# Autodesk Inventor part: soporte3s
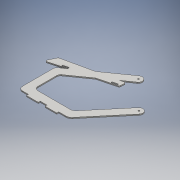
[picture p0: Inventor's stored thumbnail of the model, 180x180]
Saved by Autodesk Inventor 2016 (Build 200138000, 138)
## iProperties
Created: 2016-06
Part Number: soporte3s
Material: Genérico
Document SubType Name: Modeling
Designer: adm
Density: 1 g/cm^3
Appearance: Valor por defecto
Author: adm
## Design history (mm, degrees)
sketch "Boceto1"
  geometry: L1 (-161.273, -190.979)-(3.65, -190.979); L2 (-109.73, -230.979)-(-75.003, -230.979); L3 (-109.73, -230.979)-(-75.003, -230.979); L4 (-75.003, -230.979)-(-75.003, -240.979); L5 (-75.003, -230.979)-(-75.003, -240.979); L6 (-75.003, -240.979)-(-15.003, -240.979); L7 (-75.003, -240.979)-(-15.003, -240.979); L8 (-15.003, -240.979)-(-15.003, -230.979); L9 (-15.003, -240.979)-(-15.003, -230.979); L10 (-15.003, -230.979)-(22.302, -230.979); L11 (-109.73, -240.979)-(-109.73, -230.979); L12 (-181.273, -74.736)-(-181.273, -170.979); L13 (-221.273, -54.025)-(-221.273, -210.979); L14 (-169.73, -230.979)-(-169.73, -240.979); L15 (-169.73, -230.979)-(-169.73, -240.979); L16 (-109.73, -240.979)-(-109.73, -230.979); L17 (-109.73, -240.979)-(-109.73, -230.979); L18 (-169.73, -240.979)-(-109.73, -240.979); L19 (-169.73, -240.979)-(-109.73, -240.979); L20 (-201.273, -230.979)-(-169.73, -230.979); L21 (-169.73, -230.979)-(-169.73, -240.979); L22 (201.715, -33.835)-(45.284, -220.263); L23 (45.284, -220.263)-(201.715, -33.835); L24 (171.073, -8.123)-(26.631, -180.263); L25 (22.169, 69.365)-(1.485, 64.788); L26 (22.169, 69.365)-(1.485, 64.788); L27 (1.485, 64.788)-(55.109, 102.688); L28 (-70.881, 13.642)-(22.812, 38.289); L29 (-172.816, -58.403)-(-70.881, 13.642); L30 (-70.881, 13.642)-(22.812, 38.289); L31 (26.532, 42.84)-(27.743, 64.115); L32 (26.532, 42.84)-(27.743, 64.115); L33 (32.022, 135.353)-(-99.407, 42.463); L34 (32.022, 135.353)-(-99.407, 42.463); L35 (-99.407, 42.463)-(-226.174, 14.411); L36 (-99.407, 42.463)-(-253.277, 8.414); L37 (-183.373, -12.849)-(-184.899, -7.046); L38 (-181.273, -15.398)-(-212.816, -37.692); L39 (-211.978, -14.169)-(-210.451, -19.972); L40 (-183.373, -12.849)-(-210.451, -19.972); L41 (-210.451, -19.972)-(-183.373, -12.849); L42 (-211.978, -14.169)-(-184.899, -7.046); L43 (-269.159, -38.518)-(-181.273, -15.398); L44 (-256.687, 5.732)-(-274.921, -31.482); L45 (-184.899, -7.046)-(-211.978, -14.169); L46 (55.109, 102.688)-(28.977, 84.219); L47 (57.428, 104.605)-(57.559, 104.42); C1 r 3.25 at (186.394, -20.979); C2 r 3.75 at (186.394, -20.979); C3 r 3.75 at (43.566, 119.021); A1 r 20 centre (-161.273, -74.736) between (-172.816, -58.403) and (-181.273, -74.736); A2 r 30 centre (3.65, -160.979) between (3.65, -190.979) and (26.631, -180.263); A3 r 30 centre (3.65, -160.979) between (3.65, -190.979) and (26.631, -180.263); A4 r 30 centre (22.302, -200.979) between (22.302, -230.979) and (45.284, -220.263); A5 r 30 centre (22.302, -200.979) between (22.302, -230.979) and (45.284, -220.263); A6 r 20 centre (-161.273, -170.979) between (-181.273, -170.979) and (-161.273, -190.979); A7 r 20 centre (-201.273, -210.979) between (-221.273, -210.979) and (-201.273, -230.979); A8 r 20 centre (186.394, -20.979) between (201.715, -33.835) and (171.073, -8.123); A9 r 20 centre (43.566, 119.021) between (55.109, 102.688) and (32.022, 135.353); A10 r 5 centre (22.751, 64.399) between (27.743, 64.115) and (22.169, 69.365); A11 r 5 centre (22.751, 64.399) between (27.743, 64.115) and (21.183, 69.147); A12 r 5 centre (21.54, 43.125) between (22.812, 38.289) and (26.532, 42.84); A13 r 5 centre (21.54, 43.125) between (22.812, 38.289) and (26.532, 42.84); A14 r 20 centre (-201.273, -54.025) between (-212.816, -37.692) and (-221.273, -54.025); A15 r 5 centre (-270.431, -33.682) between (-274.921, -31.482) and (-269.159, -38.518); A16 r 5 centre (-252.197, 3.532) between (-253.277, 8.414) and (-256.687, 5.732); 7 further points
  constraints: 97 end point, 36 point on circle, 19 centre point, 14 tangent, 13 point on line, 7 coincident, 7 collinear, 6 perpendicular, 3 vertical, 2 horizontal, 2 parallel
  dimensions: "d0" = 40 distance between parallel lines of L12 L13; "d1" = 20 radius of A6; "d2" = 20 radius of A7; "d3" = 20 radius of A1; "d4" = 20 radius of A14; "d5" = 7.5 diameter of C2; "d6" = 160 distance of L33.end point (-255.628, 7.894); "d7" = 7.5 diameter of C3; "d8" = 5 radius of A16; "d9" = 5 radius of A15; "d12" = 10 distance between parallel lines of L18 L20; "d13" = 10 distance between parallel lines of L2 L6
extrude "Extrusión1" new body sketch "Boceto1" distance "d10" = 6; taper "d11" = 0 deg
sketch "Boceto2"
  geometry: L1 (-99.407, 42.463)-(-253.277, 8.414); L2 (-99.407, 42.463)-(-226.174, 14.411); L3 (-70.881, 13.642)-(22.812, 38.289); L4 (-172.816, -58.403)-(-70.881, 13.642); L5 (-70.881, 13.642)-(22.812, 38.289); L6 (-181.273, -74.736)-(-181.273, -170.979); L7 (-221.273, -54.025)-(-221.273, -210.979); L8 (-169.73, -230.979)-(-169.73, -238.979); L9 (-169.73, -230.979)-(-169.73, -238.979); L10 (-109.73, -230.979)-(-75.003, -230.979); L11 (-109.73, -230.979)-(-75.003, -230.979); L12 (-109.73, -238.979)-(-109.73, -230.979); L13 (-109.73, -238.979)-(-109.73, -230.979); L14 (-109.73, -238.979)-(-109.73, -230.979); L15 (-169.73, -238.979)-(-109.73, -238.979); L16 (-169.73, -238.979)-(-109.73, -238.979); L17 (-169.73, -230.979)-(-169.73, -238.979); L18 (-201.273, -230.979)-(-169.73, -230.979); L19 (-161.273, -190.979)-(3.65, -190.979); L20 (-75.003, -230.979)-(-75.003, -238.979); L21 (-75.003, -230.979)-(-75.003, -238.979); L22 (-75.003, -238.979)-(-15.003, -238.979); L23 (-75.003, -238.979)-(-15.003, -238.979); L24 (-15.003, -238.979)-(-15.003, -230.979); L25 (-15.003, -238.979)-(-15.003, -230.979); L26 (-15.003, -230.979)-(22.302, -230.979); L27 (-10.145, 32.721)-(-11.724, 38.721); L28 (-11.724, 38.721)-(-10.145, 32.721); L29 (32.022, 135.353)-(-99.407, 42.463); L30 (32.022, 135.353)-(-99.407, 42.463); L31 (-10.145, 32.721)-(16.933, 39.845); L32 (-11.724, 38.721)-(15.355, 45.845); L33 (15.355, 45.845)-(-11.724, 38.721); L34 (15.355, 45.845)-(16.933, 39.845); L35 (16.933, 39.845)-(15.355, 45.845); L36 (26.532, 42.84)-(27.743, 64.115); L37 (26.532, 42.84)-(27.743, 64.115); L38 (22.169, 69.365)-(1.485, 64.788); L39 (1.485, 64.788)-(55.109, 102.688); L40 (1.485, 64.788)-(55.109, 102.688); L41 (22.169, 69.365)-(1.485, 64.788); L42 (201.715, -33.835)-(45.284, -220.263); L43 (45.284, -220.263)-(201.715, -33.835); L44 (171.073, -8.123)-(26.631, -180.263); L45 (-183.373, -12.849)-(-184.899, -7.046); L46 (-181.273, -15.398)-(-212.816, -37.692); L47 (-211.978, -14.169)-(-210.451, -19.972); L48 (-183.373, -12.849)-(-210.451, -19.972); L49 (-210.451, -19.972)-(-183.373, -12.849); L50 (-211.978, -14.169)-(-184.899, -7.046); L51 (-184.899, -7.046)-(-211.978, -14.169); L52 (-269.159, -38.518)-(-181.273, -15.398); L53 (-256.687, 5.732)-(-274.921, -31.482); C1 r 3.25 at (186.394, -20.979); C2 r 3.75 at (186.394, -20.979); C3 r 3.25 at (43.566, 119.021); C4 r 3.75 at (43.566, 119.021); A1 r 20 centre (-161.273, -74.736) between (-172.816, -58.403) and (-181.273, -74.736); A2 r 20 centre (-161.273, -170.979) between (-181.273, -170.979) and (-161.273, -190.979); A3 r 20 centre (-201.273, -210.979) between (-221.273, -210.979) and (-201.273, -230.979); A4 r 30 centre (3.65, -160.979) between (3.65, -190.979) and (26.631, -180.263); A5 r 30 centre (3.65, -160.979) between (3.65, -190.979) and (26.631, -180.263); A6 r 30 centre (22.302, -200.979) between (22.302, -230.979) and (45.284, -220.263); A7 r 30 centre (22.302, -200.979) between (22.302, -230.979) and (45.284, -220.263); A8 r 5 centre (21.54, 43.125) between (22.812, 38.289) and (26.532, 42.84); A9 r 5 centre (21.54, 43.125) between (22.812, 38.289) and (26.532, 42.84); A10 r 5 centre (22.751, 64.399) between (27.743, 64.115) and (22.169, 69.365); A11 r 5 centre (22.751, 64.399) between (27.743, 64.115) and (21.183, 69.147); A12 r 20 centre (186.394, -20.979) between (201.715, -33.835) and (171.073, -8.123); A13 r 20 centre (43.566, 119.021) between (55.109, 102.688) and (32.022, 135.353); A14 r 5 centre (-270.431, -33.682) between (-274.921, -31.482) and (-269.159, -38.518); A15 r 5 centre (-252.197, 3.532) between (-253.277, 8.414) and (-256.687, 5.732); A16 r 20 centre (-201.273, -54.025) between (-212.816, -37.692) and (-221.273, -54.025); 7 further points
  constraints: 109 end point, 35 point on circle, 20 centre point, 14 tangent, 11 point on line, 9 collinear, 9 perpendicular, 8 coincident, 3 vertical, 2 horizontal, 2 parallel
  dimensions: "d14" = 40 distance between parallel lines of L6 L7; "d15" = 20 radius of A2; "d16" = 20 radius of A3; "d17" = 20 radius of A1; "d18" = 20 radius of A16; "d19" = 7.5 diameter of C2; "d20" = 160 distance of L1.start point (-255.628, 7.894); "d21" = 7.5 diameter of C4; "d22" = 5 radius of A15; "d23" = 5 radius of A14
extrude "Extrusión2" cut sketch "Boceto2" distance "d24" = 6; taper "d25" = 0 deg
node "Sólido1"
other parameters: "d30" = 3, "d34" = 35
